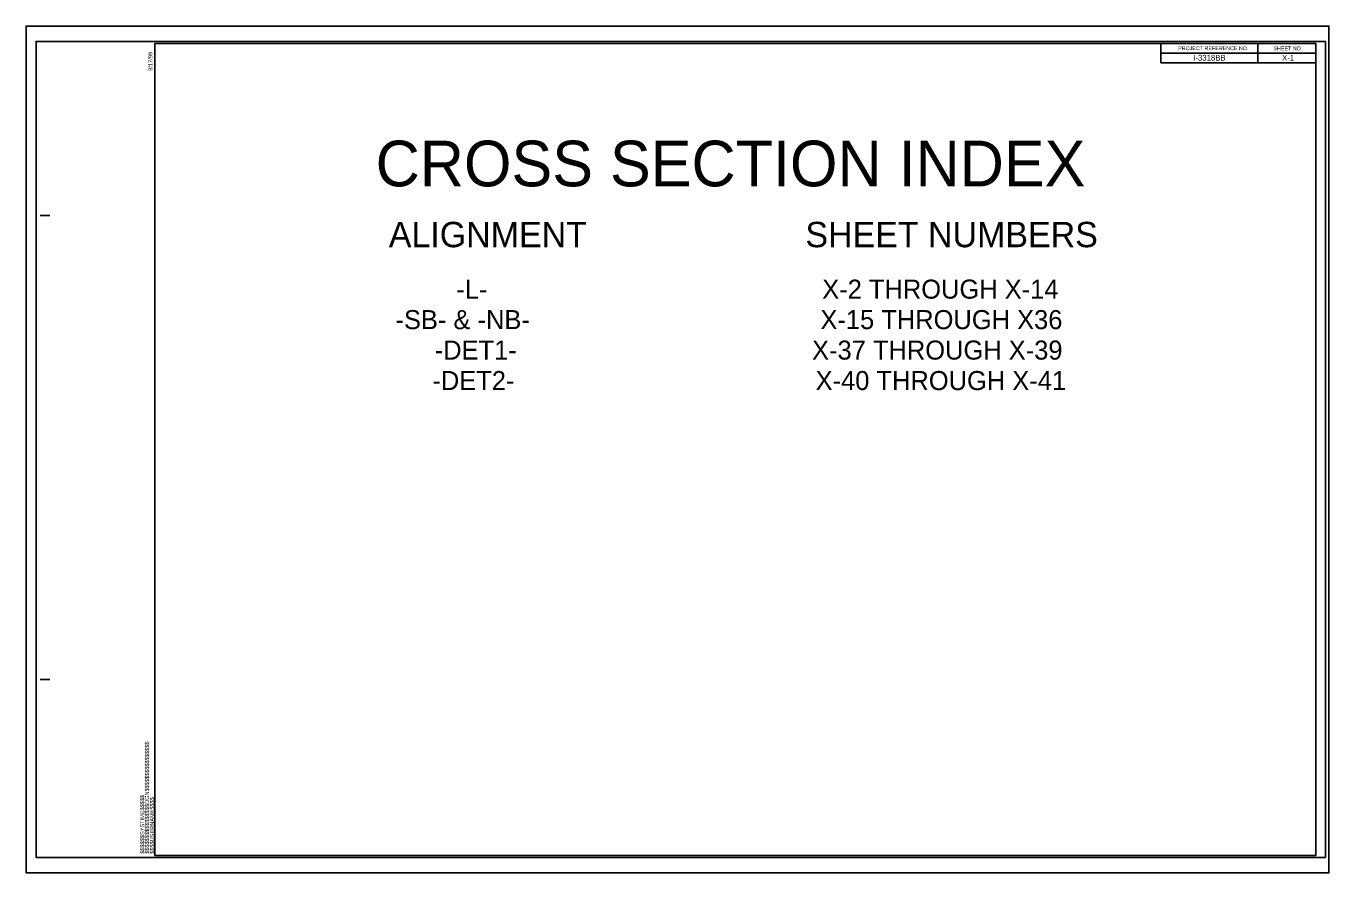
# Model space of a CAD drawing. Extents: x 3250 to 6146, y 3468 to 4563.
# Drawn here: x 3250 to 4933, y 3468 to 4563 of the extents above; entities that cross this region are included whole.
import ezdxf

# ---------------------------------------------------------------- set-up
doc = ezdxf.new("R2010")
doc.units = 0
for name, color, linetype in [('Old_Level_4', 7, 'Continuous'), ('Sheet Cutting Line CELL', 7, 'Continuous'), ('Sheet Data Field CELL', 7, 'Continuous'), ('Sheet Plan CELL', 7, 'Continuous'), ('Sheet Plot Border Inside CELL', 7, 'Continuous'), ('Sheet Plot Border Outside CELL', 7, 'Continuous')]:
    doc.layers.add(name, color=color, linetype=linetype)

msp = doc.modelspace()

# ---------------------------------------------------------------- linework, layer by layer
at = {"layer": 'Sheet Cutting Line CELL'}
for p, q in [((4933.2, 4562.9), (3249.7, 4562.9)), ((3249.7, 4562.9), (3249.7, 3467.9)), ((3249.7, 3467.9), (4933.2, 3467.9))]:
    msp.add_line(p, q, dxfattribs=at)
at = {"layer": 'Sheet Plan CELL'}
for p, q in [((3416.2, 4540.4), (3416.2, 4540.4)), ((4841.1, 4540.3), (4841.2, 4515.3)), ((4716.1, 4527.8), (4916.2, 4527.8)), ((4716.1, 4515.3), (4916.2, 4515.3)), ((4716.1, 4515.3), (4916.2, 4515.3)), ((4916.2, 4502.8), (4916.2, 4390.3)), ((3267.7, 4317.8), (3280.2, 4317.9)), ((3267.7, 3717.9), (3280.2, 3717.8)), ((3416.2, 3490.4), (3416.2, 3490.4))]:
    msp.add_line(p, q, dxfattribs=at)
for points in [[(3416.2, 3490.4), (3416.1, 4540.3), (4716.1, 4540.5), (4716.1, 4515.3), (4916.1, 4515.3), (4916.2, 3490.4)], [(4916.2, 4540.4), (3416.2, 4540.4), (3416.2, 3490.4), (4916.2, 3490.4)], [(4716.1, 4540.4), (4916.2, 4540.4), (4916.2, 4515.3), (4716.1, 4515.3)]]:
    msp.add_lwpolyline(points, close=True, dxfattribs=at)
at = {"layer": 'Sheet Plot Border Inside CELL'}
msp.add_lwpolyline([(3262.7, 3487.9), (4928.7, 3487.9), (4928.7, 4542.9), (3262.7, 4542.9)], close=True, dxfattribs=at)
at = {"layer": 'Sheet Plot Border Outside CELL'}
msp.add_lwpolyline([(3249.7, 3467.9), (4933.2, 3467.9), (4933.2, 4562.9), (3249.7, 4562.9)], close=True, dxfattribs=at)

# ---------------------------------------------------------------- texts
at = {"layer": 'Old_Level_4'}
for s, height, p in [('CROSS SECTION INDEX', 59.055, (3701.4, 4355.6)), ('ALIGNMENT', 32.81, (3718.4, 4276.9)), ('SHEET NUMBERS', 32.808, (4256.7, 4276.9)), ('-L-', 24.61, (3805.6, 4210.4)), ('X-2 THROUGH X-14', 24.606, (4278.4, 4210.4)), ('-SB- & -NB-', 24.606, (3727, 4171)), ('X-15 THROUGH X36', 24.606, (4276.1, 4171)), ('-DET1-', 24.61, (3777.7, 4131.6)), ('X-37 THROUGH X-39 ', 24.606, (4265.3, 4131.6)), ('-DET2-', 24.61, (3774.7, 4092.2)), ('X-40 THROUGH X-41', 24.606, (4269.9, 4092.2))]:
    msp.add_text(s, height=height, dxfattribs=at).set_placement(p)
at = {"layer": 'Sheet Data Field CELL'}
for s, p in [('I-3318BB', (4757.8, 4518.1)), ('X-1', (4872.6, 4518.1))]:
    msp.add_text(s, height=7.5, rotation=0, dxfattribs=at).set_placement(p)
at = {"layer": 'Sheet Plan CELL'}
for s, height, rotation, p in [('PROJECT REFERENCE NO.', 5, 0, (4738.3, 4531.7)), ('SHEET NO.', 5, 0, (4861.5, 4531.5)), ('8/17/99', 5.25, 90, (3412.9, 4505.1)), ('$$$$$$$$$$$$$$$$DGN$$$$$$$$$$$$$$$$', 5.25, 90, (3408.5, 3492.7)), ('$$$$$$SYSTIME$$$$$', 5.25, 90, (3402.4, 3492.7)), ('$$$$USERNAME$$$$', 5.25, 90, (3415.1, 3492.7))]:
    msp.add_text(s, height=height, rotation=rotation, dxfattribs=at).set_placement(p)

doc.saveas('drawing.dxf')
